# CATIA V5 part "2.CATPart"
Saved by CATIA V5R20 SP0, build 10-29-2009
Part number: 2
Bounding box of the stored display mesh (mm): x -166.445 to 166.445, y -168.043 to 168.043, z -40 to 308.251
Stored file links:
  E:\Ehsan\Amoozesh\CATIA\CATIA Course\Advanced\Videos\Session-25\2.CATPart
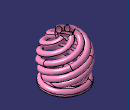
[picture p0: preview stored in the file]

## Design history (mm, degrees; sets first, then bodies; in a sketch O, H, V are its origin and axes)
AxisSystem1: origin (0, 0, 0), X (1, 0, 0), Y (0, 1, 0), Z (0, 0, 1)
Set1
  Revol1: Element1 Sketch4, Angle1 360, Line Sketch4.V
  Sketch1 on YZ plane of AxisSystem1, origin (0, 0, 0), H (0, 1, 0), V (0, 0, 1)
    line L1 (0, -40) -> (0, 290)
    point P1 (0, -40)
    reference projected line E1 (180, -40) -> (-180, -40) from edge of Revol1
    length L1 = 330
    coincidence: P1 V, P1 E1
    vertical: L1 V
  Sketch2 on YZ plane of AxisSystem1, origin (0, 0, 0), H (0, 1, 0), V (0, 0, 1)
    line L1 (0, -40) -> (180, -40)
    point P1 (0, -40)
    reference projected point E1 (0, -40) from Sketch1.P1
    length L1 = 180
    coincidence: P1 V, P1 E1
    horizontal: L1 H
  Sweep1: type Unspec, Profile Sketch2, Guide Sketch1, Reference yz-plane, RefAngle 0, RefAngle2 360
  Sketch3 on YZ plane of AxisSystem1, origin (0, 0, 0), H (0, 1, 0), V (0, 0, 1)
    reference projected line E1 (180, 290) -> (0, 290) from edge of Sweep1
    reference projected line E2 (0, -40) -> (180, -40) from Sketch2.L1
    spline S1 through (50, 290) (130, 210) (130, 40) (50, -40)
    point P5 (50, 290)
    point P6 (50, -40)
    point P7 (130, 40)
    point P8 (130, 210)
    distance P6 V = 50
    distance P7 V = 130
    distance P8 V = 130
    distance P5 V = 50
    distance P7 E2 = 80
    distance P8 E1 = 80
    coincidence: P5 E1, P6 E2
  Revol2: Element1 Sketch3, Angle1 360, Line Sketch1
  Intersect1: ToIntersect1 Revol2, ToIntersect2 Sweep1
  Sweep2: type Circle, Guide Intersect1, Radius 20
  CircPattern1: of Sweep2, instances 6, angular step 60 {= 360.0*1 deg/CircPattern1.AngularNumber}, axis from edge [ZX plane of AxisSystem1 | YZ plane of AxisSystem1]
  Trim1: Trimmed (CircPattern1; Revol1)
  Trim2: Trimmed (Sweep2; Trim1)
Body1 (main body)
  Sketch4 on YZ plane of AxisSystem1, origin (0, 0, 0), H (0, 1, 0), V (0, 0, 1)
    line L1 (0, 0) -> (135, 0)
    point P1 (160, 0)
    line L2 (160, -25) -> (160, -40)
    point P2 (160, -40)
    arc A1 centre (135, -25) radius 25 from (135, 0) to (160, -25) cw
    distance O P1 = 160
    distance P1 P2 = 40
    radius A1 = 25
    horizontal: L1 H
    vertical: L2 V
    coincidence: L1 P1, L2 P1
    tangency: A1 L1, A1 L2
